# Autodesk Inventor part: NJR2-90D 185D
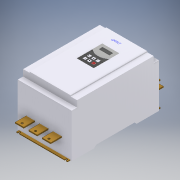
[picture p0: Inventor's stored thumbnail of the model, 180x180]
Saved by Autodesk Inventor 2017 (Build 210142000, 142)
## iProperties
Part Number: NJR2-90D 185D
Material: Типовые
Document SubType Name: Modeling
Designer: RSagdiev
Density: 1 g/cm^3
Appearance: По умолчанию
Author: RSagdiev
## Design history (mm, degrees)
sketch "Эскиз1"
  geometry: L1 (0, 0)-(15.898, 0) reference; L2 (0, 0)-(0, 16.101) reference; L3 (0, 0)-(105, 0); L4 (410, 0)-(410, 206); L5 (410, 241)-(0, 241); L6 (0, 241)-(0, 206); L7 (115, -10)-(295, -10); L8 (295, -10)-(295, 0); L9 (295, 10)-(115, 10); L10 (115, 10)-(115, 10); L11 (115, -10)-(295, 10); L12 (295, -10)-(115, 10); L13 (305, 0)-(410, 0); L14 (115, 0)-(205, 0); L15 (205, 0)-(295, 0); L16 (295, 10)-(295, 10); L17 (115, 0)-(115, -10); L18 (295, 10)-(305, 0); L19 (115, 10)-(105, 0); L20 (410, 241)-(385, 241); L21 (385, 241)-(385, 206); L22 (385, 206)-(410, 206); L23 (410, 206)-(410, 241); L24 (0, 241)-(25, 241); L25 (25, 241)-(25, 206); L26 (25, 206)-(0, 206); L27 (0, 206)-(0, 241); L28 (410, 206)-(410, 241); L29 (0, 206)-(0, 0); 1 further point
  constraints: 58 end point, 17 parallel, 12 perpendicular, 9 horizontal, 4 midpoint, 4 point on line, 2 vertical, 1 other
  dimensions: "d0" = 410 distance of L5.end L5.start; "d1" = 241 distance of L5.start L4.start; "d2" = 180 distance of L9.end L9.start; "d3" = 20 distance of L9.start L7.end; "d4" = 205 distance from line of L14.end L4 (= 0.5 x d0); "d5" = 10 distance of L16.start L8.end; "d6" = 10 distance of L13.start L8.end (= d5); "d7" = 10 distance of L10.end L14.start (= d5); "d8" = 10 distance of L3.end L14.start (= d7); "d9" = 25 distance of L4.end L21.end; "d10" = 35 distance of L21.end L20.end; "d11" = 25 distance of L25.end L6.end; "d12" = 35 distance of L24.end L25.end
extrude "Выдавливание1" new body sketch "Эскиз1" stored distance "d13" = 253; taper "d14" = 0 deg
sketch "Эскиз2"
  geometry: L1 (0, 0)-(253, 0) reference; L2 (253, 360)-(253, 0) reference; L3 (253, 360)-(0, 360) reference; L4 (0, 0)-(0, 360) reference; L5 (0, 0)-(0, 360) reference; L6 (0, 0)-(253, 0) reference; L7 (0, 360)-(30, 360); L8 (30, 360)-(30, 0); L9 (30, 0)-(0, 0); L10 (0, 0)-(0, 360); L11 (253, 360)-(223, 360); L12 (223, 360)-(223, 0); L13 (223, 0)-(253, 0); L14 (253, 0)-(253, 360); 1 further point
  constraints: 16 end point, 4 parallel, 2 horizontal, 2 perpendicular, 2 point on line
  dimensions: "d15" = 30 distance of L8.end L9.end; "d16" = 30 distance of L13.end L12.end
extrude "Выдавливание2" cut sketch "Эскиз2" distance "d17" = 5; taper "d18" = 0 deg
sketch "Эскиз3"
  geometry: L1 (385, 236)-(25, 236) reference; L2 (25, 236)-(25, 206) reference; L3 (25, 206)-(0, 206) reference; L4 (0, 206)-(0, 0) reference; L5 (0, 0)-(105, 0) reference; L6 (105, 0)-(115, 10) reference; L7 (115, 10)-(295, 10) reference; L8 (295, 10)-(305, 0) reference; L9 (305, 0)-(410, 0) reference; L10 (410, 0)-(410, 206) reference; L11 (410, 206)-(385, 206) reference; L12 (385, 206)-(385, 236) reference; L13 (423, 3.5)-(315, 3.5); L14 (315, 3.5)-(315, 0.5); L15 (315, 0.5)-(423, 0.5); L16 (423, 0.5)-(423, 3.5); L17 (115, 10)-(295, 10) reference; L18 (205, 10)-(205, 236); L19 (115, 10)-(105, 0); L20 (95, 3.5)-(95, 0.5); L21 (105, 0)-(0, 0); L22 (-13, 3.5)-(95, 3.5); L23 (-13, 0.5)-(-13, 3.5); L24 (95, 0.5)-(-13, 0.5); 1 further point
  constraints: 22 end point, 4 symmetric about line, 2 midpoint, 2 parallel, 1 horizontal, 1 perpendicular
  dimensions: "d20" = 3 distance of L14.end L13.end; "d21" = 0.5 distance between parallel lines of L9 L15; "d23" = 10 distance from line of L8.end L14; "d24" = 436 distance between parallel lines of L23 L16
extrude "Выдавливание3" new body sketch "Эскиз3" stored distance "d25" = 240; taper "d26" = 0 deg
sketch "Эскиз4"
  geometry: L1 (240, 0)-(0, 0) reference; L2 (0, -108)-(0, 0) reference; L3 (240, -108)-(0, -108) reference; L4 (240, 0)-(240, -108) reference; L5 (240, 0)-(0, 0) reference; L6 (120, 0)-(120, -108); L7 (240, -108)-(0, -108) reference; L8 (240, -328)-(0, -328) reference; L9 (0, -436)-(0, -328) reference; L10 (240, -436)-(0, -436) reference; L11 (240, -328)-(240, -436) reference; L12 (10, -429.5)-(10, -436); L13 (6.5, -429.5)-(6.5, -436); L14 (13.5, -436)-(13.5, -429.5); L15 (230, -429.5)-(230, -436); L16 (226.5, -429.5)-(226.5, -436); L17 (233.5, -436)-(233.5, -429.5); C1 r 3.5 at (10, -6.5); C2 r 3.5 at (230, -6.5); A1 r 3.5 centre (10, -429.5) between (13.5, -429.5) and (6.5, -429.5); A2 r 3.5 centre (10, -436) between (6.5, -436) and (13.5, -436); A3 r 3.5 centre (230, -429.5) between (233.5, -429.5) and (226.5, -429.5); A4 r 3.5 centre (230, -436) between (226.5, -436) and (233.5, -436); 3 further points
  constraints: 18 end point, 8 point on circle, 8 tangent, 6 centre point, 4 midpoint, 2 parallel, 2 perpendicular, 2 point on line
  dimensions: "d27" = 7 diameter of C1; "d28" = 7 diameter of C2 (= d27); "d29" = 220 distance of C2.centre C1.centre; "d31" = 110 distance from line of C1.centre L6 (= 0.5 x d29); "d32" = 110 distance from line of L6 C2.centre (= d31); "d33" = 6.5 distance from line of L1 C1.centre (computed from d27); "d34" = 6.5 distance from line of L1 C2.centre (derived); "d35" = 7 diameter of A2 (= d27); "d36" = 6.5 distance from line of L10 L12.start (computed from d35); "d37" = 7 diameter of A4 (= d35); "d38" = 6.5 distance from line of L10 L15.start (= d36); "d39" = 220 distance of L15.start L12.start (= d29); "d40" = 110 horizontal distance of point (120, -423) L12.start (= d31); "d41" = 110 horizontal distance of point (120, -423) L15.start (derived)
extrude "Выдавливание4" cut sketch "Эскиз4" stored distance "d42" = 240; taper "d43" = 0 deg
node "РабПлоскость1"
sketch "Эскиз5" dims "d56" = 10, "d67" = 10
  geometry: L1 (33.5, 147)-(73.5, 147); L2 (73.5, 147)-(73.5, -367); L3 (73.5, -367)-(33.5, -367); L4 (33.5, -367)-(33.5, 147); L5 (-6.5, 95)-(246.5, 95) reference; L6 (-6.5, -20)-(-6.5, -200) reference; L7 (-6.5, -110)-(246.5, -110); L8 (246.5, -200)-(246.5, -20) reference; L9 (96.75, 147)-(136.75, 147); L10 (136.75, 147)-(136.75, -367); L11 (136.75, -367)-(96.75, -367); L12 (96.75, -367)-(96.75, 147); L13 (160, 147)-(200, 147); L14 (200, 147)-(200, -367); L15 (200, -367)-(160, -367); L16 (160, -367)-(160, 147); C1 r 5 at (53.5, 135); C2 r 5 at (116.75, 135); C3 r 5 at (180, 135); C4 r 5 at (116.75, -355); C5 r 5 at (180, -355); C6 r 5 at (53.5, -355); 1 further point
  constraints: 26 end point, 6 centre point, 3 horizontal, 3 symmetric about line, 2 midpoint, 2 parallel, 1 perpendicular, 23 other
  dimensions: "d45" = 514 distance between parallel lines of L3 L1; "d46" = 40 distance between parallel lines of L2 L4; "d48" = 257 distance between parallel lines of L1 L7 (= 0.5 x d45); "d49" = 40 distance between parallel lines of L4 L6; "d50" = 253 distance between parallel lines of L8 L6 (derived); "d53" = 63.25 distance of L1.start L9.start (= 0.25 x d50); "d59" = 10 diameter of C1; "d60" = 20 distance from line of C1.centre L4; "d61" = 12 distance from line of C1.centre L1; "d64" = 63.25 distance of C1.centre C2.centre (= d53)
extrude "Выдавливание5" new body sketch "Эскиз5" distance "d69" = 5; taper "d70" = 0 deg
node "РабПлоскость2"
sketch "Эскиз6" dims "d79" = 10, "d89" = 10
  geometry: L1 (73.5, 147)-(33.5, 147) reference; L2 (33.5, 147)-(33.5, -367) reference; L3 (33.5, -367)-(73.5, -367) reference; L4 (73.5, -367)-(73.5, 147) reference; L5 (136.75, 147)-(96.75, 147) reference; L6 (96.75, 147)-(96.75, -367) reference; L7 (96.75, -367)-(136.75, -367) reference; L8 (136.75, -367)-(136.75, 147) reference; L9 (200, 147)-(160, 147) reference; L10 (160, 147)-(160, -367) reference; L11 (160, -367)-(200, -367) reference; L12 (200, -367)-(200, 147) reference; L13 (-6.5, -110)-(246.5, -110) reference; L14 (-6.5, -10)-(246.5, -10) reference; L15 (33.5, -10)-(73.5, -10); L16 (73.5, -10)-(73.5, 162); L17 (73.5, 162)-(33.5, 162); L18 (33.5, 162)-(33.5, -10); L19 (96.75, -10)-(136.75, -10); L20 (136.75, -10)-(136.75, 162); L21 (96.75, 162)-(96.75, -10); L22 (136.75, 162)-(96.75, 162); L23 (160, -10)-(200, -10); L24 (200, -10)-(200, 162); L25 (160, 162)-(160, -10); L26 (200, 162)-(160, 162); C1 r 5 at (53.5, -355) reference; C2 r 5 at (53.5, 135) reference; C3 r 5 at (116.75, -355) reference; C4 r 5 at (116.75, 135) reference; C5 r 5 at (180, -355) reference; C6 r 5 at (180, 135) reference; C7 r 5 at (53.5, 150); C8 r 5 at (116.75, 150); C9 r 5 at (180, 150); 8 further points
  constraints: 24 end point, 3 centre point, 3 horizontal, 2 parallel, 2 point on line, 1 collinear, 1 perpendicular, 27 other
  dimensions: "d72" = 40 distance between parallel lines of L16 L18 (= d46); "d73" = 15 distance between parallel lines of L17 L1; "d76" = 63.25 distance of L1.start point (136.75, 147) (= d53); "d81" = 10 diameter of C7; "d82" = 12 distance from line of L17 C7.centre (= d61); "d83" = 20 distance from line of L18 C7.centre (= d60); "d86" = 63.25 distance of C7.centre C8.centre (= d53)
extrude "Выдавливание6" new body sketch "Эскиз6" distance "d91" = 5; taper "d92" = 0 deg
sketch "Эскиз7"
  geometry: L1 (193, -360)-(193, 0) reference; L2 (193, 0)-(0, 0) reference; L3 (0, 0)-(0, -360) reference; L4 (0, -360)-(193, -360) reference; L5 (136.5, -195)-(56.5, -195); L6 (56.5, -195)-(56.5, -119.989); L7 (56.5, -75)-(136.5, -75); L8 (136.5, -75)-(136.5, -119.721); L9 (136.5, -195)-(56.5, -75); L10 (56.5, -195)-(136.5, -75); L11 (136.7, -74.8)-(56.3, -74.8); L12 (56.3, -74.8)-(56.3, -195.2); L13 (56.3, -195.2)-(136.7, -195.2); L14 (136.7, -195.2)-(136.7, -74.8); L15 (136.5, -119.721)-(136.5, -119.989); L16 (136.5, -119.989)-(136.5, -195); L17 (56.5, -119.721)-(56.5, -75); L18 (56.5, -119.989)-(56.5, -119.721); L19 (72.5, -88.361)-(120.5, -88.361); L20 (121.5, -89.361)-(121.5, -105.361); L21 (120.5, -106.361)-(72.5, -106.361); L22 (71.5, -105.361)-(71.5, -89.361); L23 (71.5, -88.361)-(121.5, -106.361); L24 (121.5, -88.361)-(71.5, -106.361); L25 (96.5, -135)-(96.5, -195.2); L26 (76.5, -131.781)-(76.5, -195); L27 (116.5, -131.781)-(116.5, -195); L28 (56.5, -175)-(136.5, -175); L29 (56.5, -155)-(136.5, -155); L30 (70.5, -149)-(82.5, -149); L31 (82.5, -149)-(82.5, -161); L32 (82.5, -161)-(70.5, -161); L33 (70.5, -161)-(70.5, -149); L34 (70.5, -149)-(82.5, -161); L35 (82.5, -149)-(70.5, -161); L36 (70.5, -169)-(82.5, -169); L37 (82.5, -169)-(82.5, -181); L38 (82.5, -181)-(70.5, -181); L39 (70.5, -181)-(70.5, -169); L40 (70.5, -169)-(82.5, -181); L41 (82.5, -169)-(70.5, -181); L42 (110.5, -149)-(122.5, -149); L43 (122.5, -149)-(122.5, -161); L44 (122.5, -161)-(110.5, -161); L45 (110.5, -161)-(110.5, -149); L46 (110.5, -149)-(122.5, -161); L47 (122.5, -149)-(110.5, -161); L48 (110.5, -169)-(122.5, -169); L49 (122.5, -169)-(122.5, -181); L50 (122.5, -181)-(110.5, -181); L51 (110.5, -181)-(110.5, -169); L52 (110.5, -169)-(122.5, -181); L53 (122.5, -169)-(110.5, -181); L54 (90.5, -149)-(102.5, -149); L55 (102.5, -149)-(102.5, -161); L56 (102.5, -161)-(90.5, -161); L57 (90.5, -161)-(90.5, -149); L58 (90.5, -149)-(102.5, -161); L59 (102.5, -149)-(90.5, -161); L60 (90.5, -169)-(102.5, -169); L61 (102.5, -169)-(102.5, -181); L62 (102.5, -181)-(90.5, -181); L63 (90.5, -181)-(90.5, -169); L64 (90.5, -169)-(102.5, -181)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; A1 r 60 centre (96.5, -75) between (56.5, -119.721) and (136.5, -119.721); A2 r 60.2 centre (96.5, -75) between (56.5, -119.989) and (136.5, -119.989); A3 r 1 centre (72.5, -89.361) between (72.5, -88.361) and (71.5, -89.361); A4 r 1 centre (72.5, -105.361) between (71.5, -105.361) and (72.5, -106.361); A5 r 1 centre (120.5, -105.361) between (120.5, -106.361) and (121.5, -105.361); A6 r 1 centre (120.5, -89.361) between (121.5, -89.361) and (120.5, -88.361); 8 further points
  constraints: 122 end point, 26 parallel, 23 point on line, 20 midpoint, 14 point on circle, 13 perpendicular, 8 horizontal, 8 tangent, 6 centre point, 3 equal radius, 1 vertical
  dimensions: "d93" = 80 distance of L7.start L7.end; "d94" = 120 distance of L5.end L7.start; "d95" = 75 distance between parallel lines of L2 L7; "d96" = 56.5 distance between parallel lines of L3 L6; "d97" = 0.2 distance between parallel lines of L7 L11; "d98" = 60 radius of A1; "d99" = 0.2 radial gap between concentric circles of A1 A2; "d100" = 0.2 distance between parallel lines of L6 L12; "d101" = 0.2 distance between parallel lines of L16 L14; "d102" = 0.2 distance between parallel lines of L5 L13; "d103" = 50 distance of L23.end L24.end; "d104" = 18 distance of L24.start L23.end; "d105" = 1 radius of A3; "d106" = 13.36068 distance between parallel lines of L7 L19; "d107" = 15 distance between parallel lines of L17 L22; "d108" = 20 distance between parallel lines of L25 L26 (= 0.25 x d93); "d109" = 20 horizontal distance of L25.end L27.end (= d108); "d110" = 20 distance between parallel lines of L5 L28 (= d108); "d111" = 20 distance between parallel lines of L28 L29 (= d108); "d112" = 12 distance of L31.end L32.end; "d113" = 12 distance of L30.end L31.end; "d114" = 12 distance of L37.end L38.end; "d115" = 12 distance of L36.end L37.end; "d116" = 12 distance of L43.end L44.end; "d117" = 12 distance of L42.end L43.end; "d118" = 12 distance of L49.end L50.end; "d119" = 12 distance of L48.end L49.end; "d120" = 12 distance of L55.end L56.end; "d121" = 12 distance of L54.end L55.end; "d122" = 12 distance of L61.end L62.end; "d123" = 12 distance of L60.end L61.end
  node "Спроецированная петля8"
extrude "Выдавливание7" cut sketch "Эскиз7" distance "d124" = 10; taper "d125" = 0 deg
extrude "Выдавливание8" cut sketch "Эскиз7" distance "d126" = 1; taper "d127" = 0 deg
extrude "Выдавливание9" cut sketch "Эскиз7" distance "d128" = 0.1; taper "d129" = 0 deg
sketch "Эскиз8" dims "d139" = 7, "d140" = 7
  geometry: L1 (0, 12)-(0, 0) reference; L2 (1, 4)-(10.784, 4); L3 (0, 0)-(12, 0) reference; L4 (43, 4)-(49.667, 4); L5 (3, -16)-(9.899, -16); L6 (42, -16)-(49.667, -16); L7 (0, -8)-(0, -20) reference; L8 (40, 12)-(40, 0) reference; L9 (40, -8)-(40, -20) reference; L10 (40, 0)-(52, 0) reference; L11 (40, -20)-(52, -20) reference; L12 (0, -20)-(12, -20) reference; L13 (20, 12)-(20, 0) reference; L14 (20, 0)-(32, 0) reference; L15 (32, 0)-(32, 12) reference; L16 (32, 12)-(20, 12) reference; L17 (20, -8)-(20, -20) reference; L18 (20, -20)-(32, -20) reference; L19 (32, -20)-(32, -8) reference; L20 (32, -8)-(20, -8) reference; L21 (20, 12)-(32, 0); L22 (32, 0)-(32, 12) reference; L23 (32, 12)-(20, 0); L24 (32, -8)-(20, -8) reference; L25 (20, -8)-(32, -20); L26 (32, -8)-(20, -20); L27 (26, 9.5)-(29.031, 4.25); L28 (29.031, 4.25)-(22.969, 4.25); L29 (22.969, 4.25)-(26, 9.5); L30 (26, -17.5)-(22.969, -12.25); L31 (22.969, -12.25)-(29.031, -12.25); L32 (29.031, -12.25)-(26, -17.5); 5 further points
  constraints: 28 end point, 8 horizontal, 2 coincident, 2 midpoint, 2 perpendicular, 2 vertical alignment, 18 other
  dimensions: "d130" = 1 distance from line of L1 L2.start; "d131" = 4 distance between parallel lines of L3 L2; "d133" = 3 distance from line of L7 L5.start; "d134" = 3 distance from line of L8 L4.start; "d135" = 2 distance from line of L9 L6.start; "d136" = 4 distance between parallel lines of L10 L4 (= d131); "d137" = 4 distance between parallel lines of L11 L6 (= d131); "d138" = 4 distance between parallel lines of L12 L5 (= d131)
  node "Спроецированная петля9"
  node "Спроецированная петля10"
feature "Рельеф1" dims "d141" = 0.1, "d142" = 0
feature "Рельеф2" dims "d143" = 0.1, "d144" = 0
feature "Рельеф3" dims "d145" = 0.1, "d146" = 0
feature "Рельеф4" dims "d147" = 0.1, "d148" = 0
feature "Рельеф5" dims "d149" = 0.1, "d150" = 0
feature "Рельеф6" dims "d151" = 0.1, "d152" = 0
sketch "Эскиз9"
  geometry: L1 (61.3, -40)-(127.615, -40); L2 (56.3, -195.2)-(56.3, -74.8) reference; L3 (-30, 0)-(223, 0) reference; 1 further point
  constraints: 2 end point, 2 horizontal
  dimensions: "d153" = 5 distance from line of L2 L1.start; "d154" = 40 distance between parallel lines of L3 L1
feature "Рельеф7" sketch "Эскиз9" dims "d155" = 0.1, "d156" = 0
node "Твердое тело1"
node "Спроецированная петля1"
node "Спроецированная петля2"
node "Твердое тело2"
node "Спроецированная петля3"
node "Спроецированная петля4"
node "Твердое тело3"
node "Спроецированная петля5"
node "Спроецированная петля6"
node "Спроецированная петля7"
node "Твердое тело4"
other parameters: "d71" = -35
